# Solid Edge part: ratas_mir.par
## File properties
Author: Georg
Template: Iso Part.par
Last saved by: Georg
Revision: 3
Application: Solid Edge
Accuracy: 0,990
Username: Georg
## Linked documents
ratas.par
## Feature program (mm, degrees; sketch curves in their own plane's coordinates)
part copy "CopiedPart_1"
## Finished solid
Body 1: solid body, 5 faces, 4 edges, 0 vertices.
  Faces by surface: plane 3, cylinder 2
  Edges by curve: circle 4
Bounding box of the edges (mm): 30.000 x 12.000 x 30.000, from (13.8781, 0, -41.601) to (43.8781, 12, -11.601).
Cylindrical faces by radius (mm): R10 x1, R15 x1
Planar faces by outward normal: +y 2, -y 1
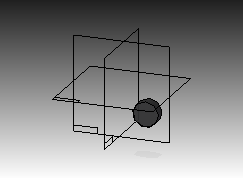
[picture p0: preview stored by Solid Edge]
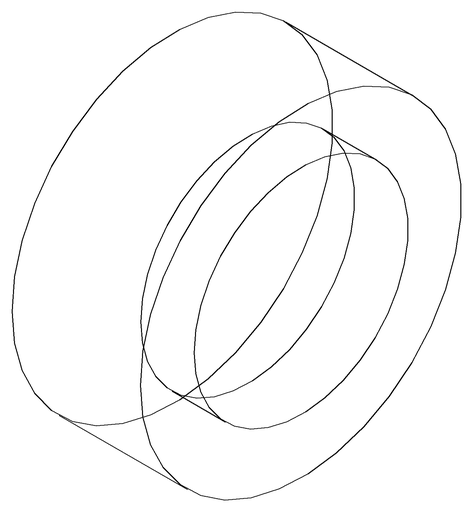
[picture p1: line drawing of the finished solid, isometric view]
